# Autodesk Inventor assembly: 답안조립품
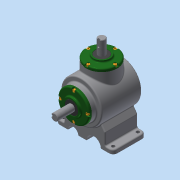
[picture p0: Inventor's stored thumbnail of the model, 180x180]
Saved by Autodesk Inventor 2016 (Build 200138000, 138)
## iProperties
Created: 2018-08
Part Number: 답안조립품
Material: 일반
Document SubType Name: Assembly
Designer: 605-07
Author: 605-07
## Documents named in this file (14)
- C:\Users\605-07\Desktop\480807V1024\답안조립품.iam
- C:\Users\605-07\Desktop\480807V1024\본체.ipt
- C:\Users\605-07\Desktop\480807V1024\메인 베벨기어.ipt
- C:\Users\605-07\Desktop\480807V1024\메인 축.ipt
- 메인 축.ipt
- C:\Users\605-07\Desktop\480807V1024\베어링 6203.ipt
- C:\Users\605-07\Desktop\480807V1024\볼트 M4.ipt
- C:\Users\605-07\Desktop\480807V1024\서브 베벨기어.ipt
- C:\Users\605-07\Desktop\480807V1024\서브 축.ipt
- 서브 축.ipt
- C:\Users\605-07\Desktop\480807V1024\오일실 17 32 8.ipt
- C:\Users\605-07\Desktop\480807V1024\커버.ipt
- C:\Users\605-07\Desktop\480807V1024\키 4x4.ipt
- C:\Users\605-07\Desktop\480807V1024\키 5x5.ipt
